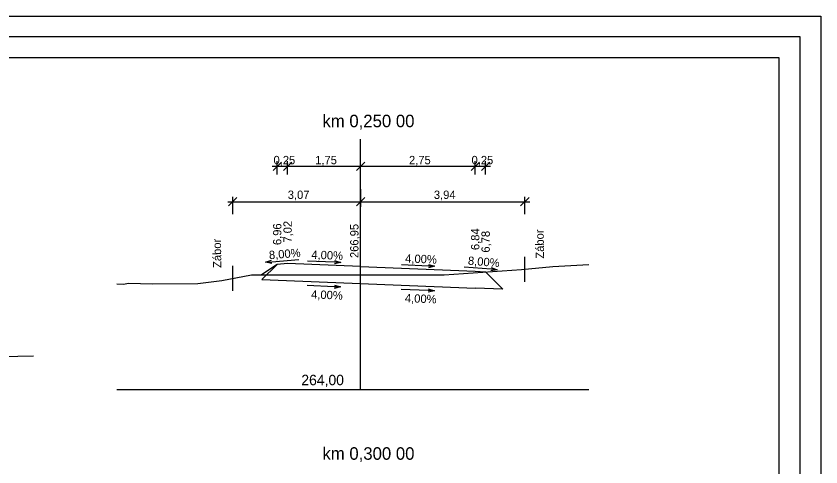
# Model space of a CAD drawing. Extents: x -763510.2 to -763467.2, y -1048902.9 to -1048872.2.
# Drawn here: x -763486.51 to -763467.21, y -1048883 to -1048872.18 of the extents above; entities that cross this region are included whole.
import ezdxf

# ---------------------------------------------------------------- set-up
doc = ezdxf.new("R2010")
doc.units = 0
for name, color, linetype in [('C3D-KORIDOR-SPOJNICE', 7, 'Continuous'), ('C3D-POPIS', 7, 'Continuous'), ('C3D-PR-POPIS-TEREN', 7, 'Continuous'), ('C3D-PR-TEREN', 7, 'Continuous'), ('C3D-ZOBPR-NADPIS', 7, 'Continuous'), ('C3D-ZOBPR-OSY', 7, 'Continuous'), ('C3D-ZOBPR-OSY-NADPIS', 7, 'Continuous'), ('Default', 7, 'Continuous'), ('U_formát', 7, 'Continuous'), ('U_rozvržení_rámeček', 7, 'Continuous'), ('Z_Pomocná', 7, 'Continuous')]:
    doc.layers.add(name, color=color, linetype=linetype)

# ---------------------------------------------------------------- blocks, each defined once
blk = doc.blocks.new('_Oblique')
at = {"layer": 'Default'}
blk.add_line((-0.5, -0.5), (0.5, 0.5), dxfattribs=at)
blk = doc.blocks.new('_Open30')
at = {"layer": 'Default'}
for p, q in [((-1, 0.27), (0, 0)), ((0, 0), (-1, -0.27)), ((0, 0), (-1, 0))]:
    blk.add_line(p, q, dxfattribs=at)
blk = doc.blocks.new('U1096')
at = {"layer": 'Default'}
blk.add_lwpolyline([(0, -297), (0, 0), (-420, 0), (-420, -297)], close=True, dxfattribs=at)
at = {"layer": 'U_formát'}
for points in [[(-425, 5), (5, 5), (5, -302), (-425, -302)], [(-5, -292), (-5, -5), (-415, -5), (-415, -292)]]:
    blk.add_lwpolyline(points, close=True, dxfattribs=at)

msp = doc.modelspace()

# ---------------------------------------------------------------- linework, layer by layer
at = {"layer": 'C3D-KORIDOR-SPOJNICE'}
for p, q in [((-763480.252, -1048878.14), (-763480.63, -1048878.392)), ((-763480.252, -1048878.14), (-763480.618, -1048878.506)), ((-763480.002, -1048878.12), (-763480.252, -1048878.14)), ((-763478.252, -1048878.19), (-763480.002, -1048878.12)), ((-763478.252, -1048878.19), (-763475.502, -1048878.3)), ((-763475.502, -1048878.3), (-763475.252, -1048878.32)), ((-763475.252, -1048878.32), (-763474.836, -1048878.737)), ((-763475.252, -1048878.32), (-763475.251, -1048878.321)), ((-763480.618, -1048878.506), (-763475.502, -1048878.71)), ((-763474.836, -1048878.737), (-763475.502, -1048878.71))]:
    msp.add_line(p, q, dxfattribs=at)
at = {"layer": 'C3D-POPIS'}
for p, q in [((-763480.372, -1048875.787), (-763478.132, -1048875.787)), ((-763480.252, -1048875.987), (-763480.252, -1048875.667)), ((-763480.002, -1048875.987), (-763480.002, -1048875.667)), ((-763478.372, -1048875.787), (-763475.132, -1048875.787)), ((-763478.252, -1048875.987), (-763478.252, -1048875.667)), ((-763475.502, -1048875.987), (-763475.502, -1048875.667)), ((-763475.252, -1048875.987), (-763475.252, -1048875.667))]:
    msp.add_line(p, q, dxfattribs=at)
for points in [[(-763480.383, -1048878.075), (-763479.735, -1048878.024)], [(-763478.875, -1048878.09), (-763479.524, -1048878.064)], [(-763476.625, -1048878.18), (-763477.274, -1048878.154)], [(-763475.122, -1048878.255), (-763475.77, -1048878.204)], [(-763478.882, -1048878.675), (-763479.531, -1048878.649)], [(-763476.632, -1048878.765), (-763477.281, -1048878.739)]]:
    msp.add_lwpolyline(points, dxfattribs=at)
at = {"layer": 'C3D-PR-TEREN'}
for points in [[(-763484.097, -1048878.608), (-763483.936, -1048878.612), (-763483.817, -1048878.594), (-763483.24, -1048878.607), (-763482.157, -1048878.601), (-763481.578, -1048878.525), (-763480.872, -1048878.392), (-763478.699, -1048878.392), (-763478.252, -1048878.391), (-763476.247, -1048878.387), (-763474.393, -1048878.265), (-763473.637, -1048878.192), (-763472.779, -1048878.142)], [(-763496.887, -1048879.077), (-763496.334, -1048879.124), (-763495.584, -1048879.224), (-763494.83, -1048879.39), (-763493.229, -1048880.061), (-763492.998, -1048880.148), (-763491.283, -1048880.169), (-763490.093, -1048880.184), (-763489.693, -1048880.187), (-763489.569, -1048880.215), (-763488.688, -1048880.407), (-763488.306, -1048880.383), (-763487.299, -1048880.356), (-763487.225, -1048880.356), (-763486.095, -1048880.331)]]:
    msp.add_lwpolyline(points, dxfattribs=at)
at = {"layer": 'C3D-ZOBPR-OSY'}
for p, q in [((-763478.252, -1048881.137), (-763478.252, -1048875.137)), ((-763484.097, -1048881.137), (-763472.779, -1048881.137))]:
    msp.add_line(p, q, dxfattribs=at)
at = {"layer": 'Default'}
for p, q in [((-763478.252, -1048876.339), (-763478.252, -1048876.759)), ((-763478.252, -1048876.339), (-763478.252, -1048876.759)), ((-763481.318, -1048876.939), (-763481.318, -1048876.519)), ((-763474.312, -1048876.939), (-763474.312, -1048876.519)), ((-763481.438, -1048876.639), (-763478.132, -1048876.639)), ((-763478.372, -1048876.639), (-763474.192, -1048876.639))]:
    msp.add_line(p, q, dxfattribs=at)
at = {"layer": 'Z_Pomocná'}
for points in [[(-763474.312, -1048878.557), (-763474.312, -1048878.257), (-763474.312, -1048877.957)], [(-763481.318, -1048878.776), (-763481.318, -1048878.476), (-763481.318, -1048878.176)]]:
    msp.add_lwpolyline(points, dxfattribs=at)

# ---------------------------------------------------------------- block references
at = {"layer": 'C3D-POPIS'}
for name, p, xscale, yscale, rotation in [('_Oblique', (-763480.252, -1048875.787), 0.2, 0.20000000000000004, 180), ('_Oblique', (-763480.002, -1048875.787), 0.2, 0.20000000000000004, 180), ('_Oblique', (-763478.252, -1048875.787), 0.2, 0.20000000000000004, 180), ('_Open30', (-763480.532, -1048878.087), 0.14999999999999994, 0.14999999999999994, -175.4260787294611), ('_Open30', (-763478.725, -1048878.096), 0.15000000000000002, 0.15000000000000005, -2.290610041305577), ('_Open30', (-763476.475, -1048878.186), 0.15000000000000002, 0.15000000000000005, -2.290610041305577), ('_Open30', (-763474.973, -1048878.267), 0.15, 0.15, -4.573921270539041), ('_Open30', (-763478.732, -1048878.681), 0.15000000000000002, 0.15000000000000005, -2.290610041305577), ('_Open30', (-763476.482, -1048878.771), 0.15000000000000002, 0.15000000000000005, -2.290610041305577)]:
    msp.add_blockref(name, p, dxfattribs=dict(at, xscale=xscale, yscale=yscale, rotation=rotation))
at = {"layer": 'C3D-POPIS', "xscale": 0.2, "yscale": 0.20000000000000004}
for p in [(-763478.252, -1048875.787), (-763475.502, -1048875.787), (-763475.252, -1048875.787)]:
    msp.add_blockref('_Oblique', p, dxfattribs=at)
at = {"layer": 'Default', "xscale": 0.2, "yscale": 0.20000000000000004, "rotation": 180}
for p in [(-763481.318, -1048876.639), (-763478.252, -1048876.639)]:
    msp.add_blockref('_Oblique', p, dxfattribs=at)
at = {"layer": 'Default', "xscale": 0.2, "yscale": 0.20000000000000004}
for p in [(-763478.252, -1048876.639), (-763474.312, -1048876.639)]:
    msp.add_blockref('_Oblique', p, dxfattribs=at)
at = {"layer": 'U_rozvržení_rámeček', "xscale": 0.1, "yscale": 0.10000000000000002}
msp.add_blockref('U1096', (-763467.711, -1048872.685), dxfattribs=at)

# ---------------------------------------------------------------- texts
at = {"layer": 'C3D-POPIS'}
for s, p in [('0,25', (-763480.34, -1048875.738)), ('1,75', (-763479.34, -1048875.738)), ('2,75', (-763477.09, -1048875.738)), ('0,25', (-763475.59, -1048875.738))]:
    msp.add_text(s, height=0.2, dxfattribs=at).set_placement(p)
for s, rotation, p in [('6,96', 90, (-763480.152, -1048877.677)), ('7,02', 90, (-763479.902, -1048877.617)), ('266,95', 90, (-763478.302, -1048877.987)), ('266,95', 90, (-763478.302, -1048877.987)), ('6,84', 90, (-763475.402, -1048877.797)), ('6,78', 90, (-763475.152, -1048877.857)), ('8,00%', 4.5837, (-763480.441, -1048878.017)), ('4,00%', 357.7082, (-763479.435, -1048878.004)), ('4,00%', 357.7082, (-763477.185, -1048878.094)), ('8,00%', 355.4163, (-763475.682, -1048878.147)), ('4,00%', 357.7094, (-763479.441, -1048878.956)), ('4,00%', 357.7094, (-763477.191, -1048879.046))]:
    msp.add_text(s, height=0.2, rotation=rotation, dxfattribs=at).set_placement(p)
at = {"layer": 'C3D-PR-POPIS-TEREN'}
for p in [(-763473.849, -1048878), (-763481.589, -1048878.223)]:
    msp.add_text('Zábor', height=0.2, rotation=91.1271, dxfattribs=at).set_placement(p)
at = {"layer": 'C3D-ZOBPR-NADPIS'}
for s, p in [('km 0,250 00', (-763479.167, -1048874.85)), ('km 0,300 00', (-763479.167, -1048882.826))]:
    msp.add_text(s, height=0.3, rotation=360, dxfattribs=at).set_placement(p)
at = {"layer": 'C3D-ZOBPR-OSY-NADPIS'}
msp.add_text('264,00', height=0.25, dxfattribs=at).set_placement((-763479.673, -1048881.038))
at = {"layer": 'Default'}
for s, p in [('3,07', (-763479.998, -1048876.57)), ('3,94', (-763476.494, -1048876.57))]:
    msp.add_text(s, height=0.2, dxfattribs=at).set_placement(p)

doc.saveas('drawing.dxf')
